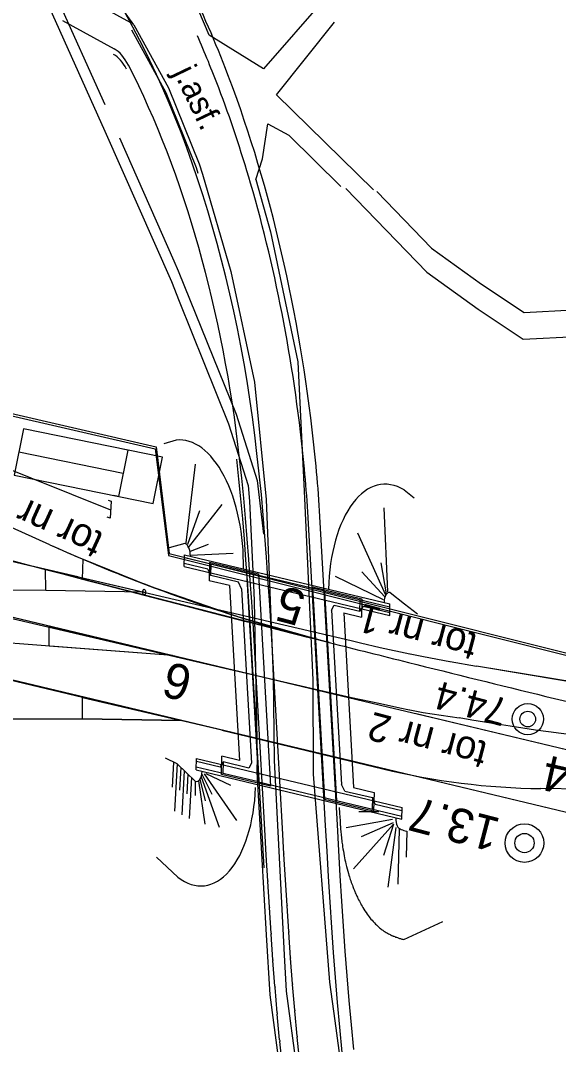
# Model space of a CAD drawing. Extents: x 6541740 to 6566395, y 5525066 to 5530361.
# Drawn here: x 6554145.9 to 6554168.66, y 5525293.06 to 5525336.42 of the extents above; entities that cross this region are included whole.
import ezdxf

# ---------------------------------------------------------------- set-up
doc = ezdxf.new("R2010")
doc.units = 0
for name, color, linetype in [('Domyślna', 7, 'Continuous'), ('TOR_PRZEK_P-komponent', 7, 'Continuous'), ('TOR_PS_OPIS_O-opisy odwodnienia', 7, 'Continuous'), ('TOR_PS_OPIS_T-symbole geometrii', 7, 'Continuous'), ('TOR_PS_OPIS_T-ukresy', 7, 'Continuous'), ('TOR_PS_T-rowy otwarte nieumocnione', 7, 'Continuous'), ('TOR_PS_T-wypelnienia', 7, 'Continuous'), ('TOR_RAMKI-ramka+tabelka 1', 7, 'Continuous'), ('TOR_W-warstwa dodatkowa 2', 7, 'Continuous')]:
    doc.layers.add(name, color=color, linetype=linetype)

# ---------------------------------------------------------------- blocks, each defined once
blk = doc.blocks.new('4010_1')
at = {"layer": 'Domyślna'}
for radius in [0.75, 0.375]:
    blk.add_circle((0, 0), radius, dxfattribs=at)
blk = doc.blocks.new('koziol 15+5')
at = {"layer": 'Domyślna'}
for p, q in [((15, 1), (14.3, 1)), ((15, 1), (15, -1)), ((20, 0), (20, 1)), ((0, 0), (15, 0)), ((15, -1), (14.3, -1))]:
    blk.add_line(p, q, dxfattribs=at)
blk.add_lwpolyline([(20, 1), (0, 1), (0, -1), (20, -1)], close=True, dxfattribs=at)
blk = doc.blocks.new('PM_2')
at = {"layer": 'Domyślna'}
blk.add_circle((0, 0), 0.25, dxfattribs=at)

msp = doc.modelspace()

# ---------------------------------------------------------------- linework, layer by layer
at = {"layer": 'TOR_PRZEK_P-komponent'}
for p, q in [((6554157.548, 5525308.274), (6554006.018, 5525344.541)), ((6554147.115, 5525310.771), (6554006.018, 5525344.541)), ((6554161.425, 5525307.346), (6554006.018, 5525344.541)), ((6554147.139, 5525314.22), (6554142.009, 5525316.524)), ((6554147.115, 5525310.771), (6554136.359, 5525313.345)), ((6554147.115, 5525310.771), (6554136.401, 5525313.335)), ((6554151.303, 5525312.499), (6554155.117, 5525311.172)), ((6554152.331, 5525309.523), (6554136.017, 5525310.789)), ((6554157.548, 5525308.274), (6554147.115, 5525310.771)), ((6554157.548, 5525308.274), (6554147.115, 5525310.771)), ((6554147.115, 5525310.771), (6554152.331, 5525309.523)), ((6554141.149, 5525309.561), (6554161.123, 5525304.78)), ((6554161.425, 5525307.346), (6554157.548, 5525308.274)), ((6554161.425, 5525307.346), (6554157.548, 5525308.274)), ((6554161.425, 5525307.346), (6554157.548, 5525308.274)), ((6554163.754, 5525306.789), (6554161.425, 5525307.346)), ((6554191.707, 5525300.099), (6554162.634, 5525307.057)), ((6554188.382, 5525300.894), (6554162.634, 5525307.057)), ((6554174.187, 5525304.292), (6554163.754, 5525306.789)), ((6554174.235, 5525304.28), (6554163.803, 5525306.777)), ((6554191.707, 5525300.099), (6554163.803, 5525306.777)), ((6554161.123, 5525304.78), (6554191.646, 5525297.475)), ((6554163.229, 5525304.276), (6554191.47, 5525297.517))]:
    msp.add_line(p, q, dxfattribs=at)
for points in [[(6554155.117, 5525311.172), (6554158.959, 5525310.078), (6554155.31, 5525311.008), (6554148.529, 5525312.766), (6554148.548, 5525313.609), (6554151.303, 5525312.499)], [(6554152.331, 5525309.523), (6554147.113, 5525309.928), (6554147.115, 5525310.771)]]:
    msp.add_lwpolyline(points, dxfattribs=at)
for centre, major_axis, start_param, end_param in [((6554272.656, 5529581.693), (-233.545, 4306.159), 2.967279, 2.979483), ((6554165.071, 5525539.713), (-12.555, 231.491), 2.884138, 2.984211), ((6554165.071, 5525539.713), (-12.555, 231.491), 2.884138, 2.89613), ((6554165.071, 5525539.713), (-12.555, 231.491), 2.89613, 2.984211), ((6554272.656, 5529581.693), (-233.545, 4306.159), 2.979483, 2.984211), ((6554272.656, 5529581.693), (-233.545, 4306.159), 2.984211, 2.985729), ((6554272.656, 5529581.693), (-233.545, 4306.159), 2.985729, 2.991005)]:
    msp.add_ellipse(centre, major_axis=major_axis, ratio=0.510219, start_param=start_param, end_param=end_param, dxfattribs=at)
at = {"layer": 'TOR_PS_OPIS_T-symbole geometrii'}
for p, q in [((6554147.253, 5525338.147), (6554150.549, 5525336.338)), ((6554147.68, 5525336.419), (6554149.866, 5525335.219)), ((6554158.806, 5525302.329), (6554158.051, 5525315.618)), ((6554159.305, 5525302.361), (6554158.55, 5525315.65)), ((6554156.985, 5525302.213), (6554156.487, 5525310.965)), ((6554156.205, 5525300.532), (6554155.614, 5525310.909)), ((6554156.236, 5525302.165), (6554155.739, 5525310.917)), ((6554156.298, 5525301.076), (6554156.236, 5525302.163)), ((6554157.047, 5525301.125), (6554156.985, 5525302.212)), ((6554156.362, 5525299.981), (6554156.299, 5525301.068)), ((6554157.11, 5525300.033), (6554157.047, 5525301.12)), ((6554156.429, 5525298.878), (6554156.363, 5525299.965)), ((6554157.177, 5525298.937), (6554157.111, 5525300.024)), ((6554156.501, 5525297.767), (6554156.43, 5525298.854)), ((6554157.248, 5525297.837), (6554157.178, 5525298.924)), ((6554156.579, 5525296.649), (6554156.503, 5525297.735)), ((6554157.325, 5525296.734), (6554157.249, 5525297.82)), ((6554157.409, 5525295.627), (6554157.326, 5525296.712)), ((6554156.664, 5525295.524), (6554156.581, 5525296.609)), ((6554156.758, 5525294.392), (6554156.668, 5525295.476)), ((6554157.502, 5525294.516), (6554157.411, 5525295.6)), ((6554157.605, 5525293.404), (6554157.504, 5525294.486)), ((6554156.864, 5525293.254), (6554156.763, 5525294.336)), ((6554156.981, 5525292.11), (6554156.87, 5525293.19)), ((6554157.719, 5525292.289), (6554157.608, 5525293.368))]:
    msp.add_line(p, q, dxfattribs=at)
for points in [[(6554156.487, 5525310.964), (6554156.429, 5525311.878), (6554156.369, 5525312.785), (6554156.307, 5525313.687), (6554156.24, 5525314.582), (6554156.168, 5525315.47), (6554156.089, 5525316.351), (6554156.002, 5525317.224), (6554155.904, 5525318.082)], [(6554155.615, 5525310.884), (6554155.557, 5525311.795), (6554155.498, 5525312.694), (6554155.437, 5525313.581), (6554155.372, 5525314.456), (6554155.302, 5525315.318), (6554155.225, 5525316.168), (6554155.142, 5525317.002), (6554155.047, 5525317.839)], [(6554155.74, 5525310.895), (6554155.682, 5525311.807), (6554155.622, 5525312.707), (6554155.561, 5525313.596), (6554155.496, 5525314.474), (6554155.425, 5525315.34), (6554155.349, 5525316.194), (6554155.265, 5525317.034), (6554155.169, 5525317.874)], [(6554159.515, 5525292.724), (6554159.406, 5525293.786), (6554159.309, 5525294.835), (6554159.221, 5525295.89), (6554159.14, 5525296.951), (6554159.066, 5525298.018), (6554158.996, 5525299.089), (6554158.931, 5525300.165), (6554158.868, 5525301.245), (6554158.806, 5525302.33)], [(6554160.007, 5525292.843), (6554159.899, 5525293.895), (6554159.804, 5525294.927), (6554159.717, 5525295.966), (6554159.637, 5525297.014), (6554159.563, 5525298.069), (6554159.495, 5525299.132), (6554159.43, 5525300.202), (6554159.367, 5525301.279), (6554159.305, 5525302.363)]]:
    msp.add_lwpolyline(points, dxfattribs=at)
for centre, major_axis, start_param, end_param in [((6554139.689, 5525313.568), (-1.756, 32.37), 4.824583, 5.588672), ((6554139.863, 5525313.698), (-1.993, 36.749), 5.240005, 5.375002), ((6554139.689, 5525313.568), (-1.96, 36.137), 5.270787, 5.346125), ((6554149.615, 5525332.866), (-0.119, 2.202), 5.429669, 5.976121), ((6554149.615, 5525332.866), (-0.133, 2.447), 5.429669, 5.976121), ((6554139.689, 5525313.568), (-1.676, 30.902), 4.824583, 5.429669), ((6554139.689, 5525313.568), (-1.96, 36.137), 5.141865, 5.270787), ((6554139.689, 5525313.568), (-2.013, 37.116), 4.791924, 5.237994), ((6554139.689, 5525313.568), (-1.96, 36.137), 4.791924, 5.141865), ((6554145.575, 5525314.817), (-1.38, 25.445), 4.71744, 4.791924), ((6554145.575, 5525314.817), (-1.327, 24.467), 4.71744, 4.791924), ((6554157.957, 5525301.184), (0.176, -3.254), 4.717851, 4.72032), ((6554157.957, 5525301.184), (0.097, -1.786), 4.717851, 4.72032), ((6554158.021, 5525300.097), (0.176, -3.254), 4.72032, 4.725259), ((6554158.021, 5525300.097), (0.097, -1.786), 4.72032, 4.725259), ((6554158.087, 5525299.01), (0.176, -3.254), 4.725259, 4.732666), ((6554158.087, 5525299.01), (0.097, -1.786), 4.725259, 4.732666), ((6554158.157, 5525297.923), (0.176, -3.254), 4.732666, 4.742543), ((6554158.157, 5525297.923), (0.097, -1.786), 4.732666, 4.742543), ((6554158.233, 5525296.837), (0.176, -3.254), 4.742543, 4.754888), ((6554158.233, 5525296.837), (0.097, -1.786), 4.742543, 4.754888), ((6554158.315, 5525295.752), (0.176, -3.254), 4.754888, 4.769703), ((6554158.315, 5525295.752), (0.097, -1.786), 4.754888, 4.769703), ((6554158.406, 5525294.668), (0.097, -1.786), 4.769703, 4.786987), ((6554158.406, 5525294.668), (0.176, -3.254), 4.769703, 4.786987), ((6554158.506, 5525293.586), (0.176, -3.254), 4.786987, 4.80674), ((6554158.506, 5525293.586), (0.097, -1.786), 4.786987, 4.80674)]:
    msp.add_ellipse(centre, major_axis=major_axis, ratio=0.510219, start_param=start_param, end_param=end_param, dxfattribs=at)
at = {"layer": 'TOR_PS_T-rowy otwarte nieumocnione'}
for p, q in [((6554142.794, 5525314.166), (6554148.327, 5525312.87)), ((6554168.968, 5525308.436), (6554165.194, 5525309.08)), ((6554154.42, 5525306.367), (6554161.231, 5525304.726)), ((6554199.007, 5525303.534), (6554167.908, 5525303.895))]:
    msp.add_line(p, q, dxfattribs=at)
for points in [[(6554103.213, 5525341.389), (6554107.185, 5525338.304), (6554111.172, 5525335.328), (6554114.839, 5525332.598), (6554120.595, 5525328.786), (6554121.88, 5525327.885), (6554125.647, 5525325.851), (6554128.763, 5525324.292), (6554131.931, 5525322.933), (6554141.308, 5525319.065), (6554149.714, 5525315.702)], [(6554100.477, 5525323.441), (6554103.102, 5525323.134), (6554105.707, 5525322.712), (6554108.194, 5525322.227), (6554110.495, 5525321.725), (6554113.375, 5525321.069), (6554125.264, 5525318.285), (6554128.426, 5525317.551), (6554136.762, 5525315.581), (6554146.963, 5525313.188), (6554153.767, 5525311.597), (6554159.892, 5525310.162), (6554159.892, 5525310.162), (6554160.286, 5525310.062), (6554161.123, 5525309.872), (6554162.378, 5525309.602), (6554162.379, 5525309.602), (6554162.943, 5525309.488), (6554164.07, 5525309.275), (6554164.071, 5525309.275), (6554165.194, 5525309.08), (6554165.194, 5525309.08)], [(6554098.464, 5525319.047), (6554100.603, 5525319.224), (6554102.799, 5525319.345), (6554105.318, 5525319.375), (6554107.923, 5525319.268), (6554110.349, 5525319.044), (6554112.65, 5525318.717), (6554115.593, 5525318.144), (6554119.723, 5525317.204), (6554128.057, 5525315.232), (6554136.392, 5525313.255), (6554137.46, 5525313.006), (6554144.268, 5525311.397), (6554153.756, 5525309.172), (6554159.899, 5525307.754), (6554161.131, 5525307.5), (6554161.954, 5525307.313), (6554162.364, 5525307.229), (6554162.366, 5525307.228), (6554162.935, 5525307.122), (6554163.314, 5525307.058), (6554164.071, 5525306.941), (6554164.072, 5525306.941), (6554164.452, 5525306.887)], [(6554154.42, 5525306.367), (6554148.523, 5525307.754), (6554140.173, 5525309.737), (6554133.36, 5525311.347), (6554115.822, 5525315.521), (6554111.041, 5525316.409), (6554107.492, 5525316.535), (6554103.892, 5525316.543), (6554099.33, 5525316.505)], [(6554149.613, 5525316.111), (6554149.737, 5525316.061), (6554149.69, 5525315.342), (6554149.566, 5525315.392)], [(6554151.131, 5525312.214), (6554146.968, 5525312.284), (6554144.262, 5525312.294), (6554140.101, 5525312.382)], [(6554151.131, 5525312.214), (6554146.968, 5525312.284), (6554144.262, 5525312.294), (6554140.101, 5525312.382)], [(6554192.925, 5525304.348), (6554190.643, 5525304.695), (6554189.694, 5525304.895), (6554189.677, 5525304.899), (6554185.348, 5525305.756), (6554165.194, 5525309.08)], [(6554098.921, 5525306.506), (6554100.881, 5525306.616), (6554103.078, 5525306.7), (6554107.887, 5525306.811), (6554111.935, 5525306.853), (6554115.391, 5525306.866), (6554123.708, 5525306.83), (6554133.482, 5525306.851), (6554148.524, 5525306.853), (6554152.691, 5525306.774)]]:
    msp.add_lwpolyline(points, dxfattribs=at)
for points in [[(6554151.131, 5525312.214), (6554146.968, 5525312.286), (6554146.963, 5525313.189)], [(6554152.691, 5525306.774), (6554148.524, 5525306.854), (6554148.523, 5525307.755)]]:
    msp.add_lwpolyline(points, close=True, dxfattribs=at)
for centre, radius, start, end in [((6554181.646, 5525405.409), 100, 260.10015, 270.11432), ((6554168.255, 5525333.893), 30, 256.4589, 269.3363)]:
    msp.add_arc(centre, radius, start, end, dxfattribs=at)
at = {"layer": 'TOR_PS_T-wypelnienia'}
for p, q in [((6554149.476, 5525332.847), (6554145.42, 5525341.912)), ((6554145.186, 5525341.277), (6554149.47, 5525331.726)), ((6554150.702, 5525336.241), (6554149.577, 5525337.806)), ((6554158.86, 5525337.443), (6554156.179, 5525334.37)), ((6554153.884, 5525335.796), (6554153.444, 5525336.824)), ((6554156.725, 5525333.277), (6554159.178, 5525336.349)), ((6554156.179, 5525334.37), (6554153.884, 5525335.796)), ((6554156.725, 5525333.277), (6554160.83, 5525329.25)), ((6554156.144, 5525330.557), (6554156.357, 5525332.041)), ((6554156.357, 5525332.041), (6554157.249, 5525331.567)), ((6554149.47, 5525331.726), (6554152.282, 5525325.36)), ((6554150.086, 5525331.45), (6554152.388, 5525326.238)), ((6554157.249, 5525331.567), (6554159.448, 5525329.387)), ((6554155.854, 5525329.688), (6554156.144, 5525330.557)), ((6554152.282, 5525325.36), (6554152.615, 5525324.533)), ((6554156.298, 5525297.705), (6554156.444, 5525295.162)), ((6554157.06, 5525296.859), (6554157.141, 5525295.313)), ((6554156.444, 5525295.162), (6554157.051, 5525290.685)), ((6554157.141, 5525295.313), (6554157.728, 5525290.98)), ((6554159.193, 5525294.054), (6554159.504, 5525291.757))]:
    msp.add_line(p, q, dxfattribs=at)
for points in [[(6554150.702, 5525336.241), (6554152.163, 5525333.561), (6554153.464, 5525330.355), (6554153.594, 5525329.912)], [(6554150.6, 5525336.027), (6554152.051, 5525333.363), (6554153.336, 5525330.197), (6554153.406, 5525329.96)], [(6554153.594, 5525329.912), (6554154.801, 5525325.795), (6554155.799, 5525321.104), (6554156.293, 5525316.135), (6554156.591, 5525308.647), (6554156.63, 5525305.085), (6554157.06, 5525296.859)], [(6554155.854, 5525329.688), (6554156.475, 5525327.466), (6554157.633, 5525321.97), (6554157.894, 5525316.492), (6554158.27, 5525308.495), (6554158.275, 5525304.511), (6554158.971, 5525295.691), (6554159.193, 5525294.054)], [(6554159.666, 5525329.311), (6554163.085, 5525325.758), (6554165.255, 5525324.196), (6554167.165, 5525322.921), (6554169.406, 5525323.042), (6554171.258, 5525323.917), (6554172.825, 5525325.293), (6554173.843, 5525325.583)], [(6554160.975, 5525329.181), (6554163.286, 5525326.78), (6554165.409, 5525325.251), (6554167.209, 5525324.049), (6554169.286, 5525324.161), (6554171.033, 5525324.987), (6554172.63, 5525326.389), (6554173.731, 5525326.698)], [(6554152.388, 5525326.238), (6554152.575, 5525325.815), (6554155.019, 5525319.742), (6554155.91, 5525316.945), (6554156.177, 5525314.67)], [(6554152.615, 5525324.533), (6554154.705, 5525319.34), (6554155.538, 5525316.724), (6554155.591, 5525316.066)], [(6554155.591, 5525316.066), (6554155.753, 5525312.512), (6554155.783, 5525311.859), (6554155.906, 5525305.229), (6554155.902, 5525304.593), (6554156.298, 5525297.705)]]:
    msp.add_lwpolyline(points, dxfattribs=at)
at = {"layer": 'TOR_W-warstwa dodatkowa 2'}
for p, q in [((6554130.54, 5525323.158), (6554151.594, 5525318.275)), ((6554130.542, 5525323.255), (6554151.634, 5525318.364)), ((6554151.634, 5525318.364), (6554152.195, 5525313.851)), ((6554152.486, 5525318.647), (6554151.969, 5525318.493)), ((6554151.594, 5525318.275), (6554152.155, 5525313.763)), ((6554152.91, 5525314.295), (6554153.307, 5525317.628)), ((6554162.129, 5525316.539), (6554162.55, 5525316.207)), ((6554153.01, 5525314.103), (6554154.43, 5525315.928)), ((6554161.44, 5525312.221), (6554161.28, 5525315.785)), ((6554152.986, 5525314.243), (6554153.485, 5525315.669)), ((6554161.356, 5525312.083), (6554160.175, 5525314.716)), ((6554152.848, 5525314.276), (6554152.195, 5525314.082)), ((6554153.09, 5525313.952), (6554153.849, 5525314.243)), ((6554152.155, 5525313.763), (6554191.772, 5525303.829)), ((6554152.195, 5525313.851), (6554191.795, 5525303.921)), ((6554152.826, 5525313.3), (6554152.837, 5525313.79)), ((6554158.768, 5525312.249), (6554152.834, 5525313.669)), ((6554152.837, 5525313.79), (6554161.53, 5525311.71)), ((6554153.086, 5525313.783), (6554154.9, 5525313.859)), ((6554152.826, 5525313.3), (6554161.519, 5525311.219)), ((6554153.832, 5525313.186), (6554152.829, 5525313.426)), ((6554153.832, 5525313.186), (6554153.952, 5525312.913)), ((6554153.902, 5525313.472), (6554153.884, 5525312.695)), ((6554155.972, 5525312.977), (6554153.902, 5525313.472)), ((6554153.952, 5525312.913), (6554153.963, 5525313.399)), ((6554161.385, 5525312.145), (6554161.153, 5525313.46)), ((6554154.748, 5525312.488), (6554153.884, 5525312.695)), ((6554155.117, 5525312.634), (6554153.952, 5525312.913)), ((6554155.468, 5525313.039), (6554155.972, 5525304.174)), ((6554155.972, 5525312.977), (6554156.483, 5525303.993)), ((6554161.26, 5525311.89), (6554159.224, 5525312.873)), ((6554161.318, 5525312.011), (6554160.34, 5525313.076)), ((6554154.748, 5525312.488), (6554155.168, 5525305.089)), ((6554155.256, 5525312.359), (6554155.117, 5525312.634)), ((6554155.256, 5525312.359), (6554155.676, 5525304.974)), ((6554158.257, 5525312.43), (6554158.768, 5525303.446)), ((6554158.257, 5525312.43), (6554160.337, 5525311.932)), ((6554158.768, 5525312.249), (6554159.272, 5525303.384)), ((6554158.768, 5525312.249), (6554161.528, 5525311.589)), ((6554160.262, 5525311.403), (6554160.273, 5525311.889)), ((6554160.337, 5525311.932), (6554160.32, 5525311.155)), ((6554159.064, 5525311.448), (6554159.176, 5525311.663)), ((6554159.064, 5525311.448), (6554159.484, 5525304.063)), ((6554159.176, 5525311.663), (6554160.262, 5525311.403)), ((6554160.393, 5525311.616), (6554160.262, 5525311.403)), ((6554160.393, 5525311.616), (6554161.522, 5525311.346)), ((6554161.519, 5525311.219), (6554161.53, 5525311.71)), ((6554159.572, 5525311.334), (6554159.992, 5525303.935)), ((6554159.572, 5525311.334), (6554160.32, 5525311.155)), ((6554152.525, 5525304.937), (6554152.032, 5525305.181)), ((6554152.371, 5525305.014), (6554152.315, 5525303.958)), ((6554152.525, 5525304.937), (6554152.42, 5525302.936)), ((6554153.335, 5525304.682), (6554153.346, 5525305.173)), ((6554154.347, 5525304.807), (6554153.344, 5525305.047)), ((6554153.346, 5525305.173), (6554162.04, 5525303.093)), ((6554154.347, 5525304.807), (6554154.478, 5525305.02)), ((6554154.403, 5525304.491), (6554154.421, 5525305.268)), ((6554155.168, 5525305.089), (6554154.421, 5525305.268)), ((6554154.478, 5525305.02), (6554154.467, 5525304.534)), ((6554155.564, 5525304.76), (6554154.478, 5525305.02)), ((6554155.676, 5525304.974), (6554155.564, 5525304.76)), ((6554152.677, 5525304.793), (6554152.626, 5525303.828)), ((6554152.828, 5525304.648), (6554152.73, 5525302.783)), ((6554152.979, 5525304.504), (6554152.935, 5525303.675)), ((6554153.335, 5525304.682), (6554162.028, 5525302.602)), ((6554155.972, 5525304.174), (6554153.338, 5525304.804)), ((6554153.574, 5525304.508), (6554153.996, 5525303.658)), ((6554153.672, 5525304.514), (6554155.033, 5525302.536)), ((6554153.743, 5525304.53), (6554154.78, 5525304.039)), ((6554156.483, 5525303.993), (6554154.403, 5525304.491)), ((6554153.13, 5525304.359), (6554153.039, 5525302.63)), ((6554153.296, 5525304.203), (6554153.29, 5525303.597)), ((6554153.43, 5525304.221), (6554153.697, 5525302.39)), ((6554153.494, 5525304.288), (6554153.716, 5525303.376)), ((6554153.543, 5525304.387), (6554154.301, 5525302.257)), ((6554155.972, 5525304.174), (6554159.272, 5525303.384)), ((6554159.623, 5525303.788), (6554159.484, 5525304.063)), ((6554159.623, 5525303.788), (6554160.788, 5525303.51)), ((6554159.992, 5525303.935), (6554160.856, 5525303.728)), ((6554160.856, 5525303.728), (6554160.838, 5525302.95)), ((6554158.768, 5525303.446), (6554160.838, 5525302.95)), ((6554159.272, 5525303.384), (6554162.031, 5525302.724)), ((6554160.788, 5525303.51), (6554160.777, 5525303.024)), ((6554160.908, 5525303.237), (6554160.788, 5525303.51)), ((6554160.908, 5525303.237), (6554162.037, 5525302.967)), ((6554161.057, 5525302.914), (6554160.21, 5525302.903)), ((6554162.028, 5525302.602), (6554162.04, 5525303.093)), ((6554161.632, 5525302.583), (6554159.671, 5525302.226)), ((6554161.685, 5525302.394), (6554159.984, 5525300.501)), ((6554161.669, 5525302.45), (6554160.31, 5525301.852)), ((6554161.686, 5525302.39), (6554161.257, 5525301.056)), ((6554161.779, 5525302.244), (6554161.436, 5525299.714)), ((6554161.922, 5525302.179), (6554161.867, 5525299.85)), ((6554162.248, 5525302.088), (6554162.221, 5525300.991)), ((6554162.124, 5525297.499), (6554163.769, 5525298.271))]:
    msp.add_line(p, q, dxfattribs=at)
for points in [[(6554161.542, 5525312.196), (6554162.141, 5525311.723), (6554162.694, 5525311.288)], [(6554159.479, 5525309.947), (6554159.479, 5525309.947)], [(6554153.291, 5525304.205), (6554152.525, 5525304.937)], [(6554152.554, 5525300.14), (6554151.659, 5525300.995)]]:
    msp.add_lwpolyline(points, dxfattribs=at)
for centre, major_axis, start_param, end_param in [((6554152.837, 5525313.79), (-0.264, 4.864), 4.561802, 6.318591), ((6554161.53, 5525311.71), (-0.275, 5.07), 5.944976, 7.703394), ((6554152.837, 5525313.79), (-0.027, 0.489), 4.561802, 6.132598), ((6554161.53, 5525311.71), (-0.027, 0.489), 6.132598, 7.703394), ((6554153.327, 5525304.701), (-0.027, 0.507), 2.898198, 4.529759), ((6554153.327, 5525304.701), (-0.267, 4.927), 2.725127, 4.529759)]:
    msp.add_ellipse(centre, major_axis=major_axis, ratio=0.510219, start_param=start_param, end_param=end_param, dxfattribs=at)
for points in [[(6554159.386, 5525303.096), (6554159.426, 5525302.384), (6554159.43, 5525302.332), (6554159.444, 5525302.144), (6554159.455, 5525302.008), (6554159.494, 5525301.665), (6554159.518, 5525301.479), (6554159.597, 5525301.016), (6554159.653, 5525300.737), (6554159.788, 5525300.247), (6554159.842, 5525300.071), (6554159.95, 5525299.768), (6554159.997, 5525299.645), (6554160.092, 5525299.422), (6554160.138, 5525299.322), (6554160.272, 5525299.048), (6554160.363, 5525298.889), (6554160.584, 5525298.544), (6554160.71, 5525298.384), (6554160.938, 5525298.133), (6554161.04, 5525298.042), (6554161.216, 5525297.9), (6554161.29, 5525297.85), (6554161.443, 5525297.754), (6554161.508, 5525297.723), (6554161.56, 5525297.698), (6554161.57, 5525297.694), (6554161.593, 5525297.683), (6554161.609, 5525297.675), (6554161.656, 5525297.655), (6554161.686, 5525297.642), (6554161.775, 5525297.606), (6554161.831, 5525297.586), (6554161.975, 5525297.538), (6554162.056, 5525297.516), (6554162.124, 5525297.499)], [(6554161.778, 5525302.662), (6554161.787, 5525302.521), (6554161.801, 5525302.266), (6554162.011, 5525302.155), (6554162.152, 5525302.112), (6554162.248, 5525302.088)]]:
    msp.add_open_spline(points, degree=3, dxfattribs=at)

# ---------------------------------------------------------------- block references
at = {"layer": 'TOR_PRZEK_P-komponent', "xscale": 0.2999999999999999, "rotation": -11.555935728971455}
msp.add_blockref('koziol 15+5', (6554145.831, 5525318.147), dxfattribs=at)
at = {"layer": 'TOR_PS_OPIS_T-ukresy', "xscale": 0.48963739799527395, "yscale": 0.25024885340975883, "rotation": 91.699535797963}
msp.add_blockref('PM_2', (6554151.131, 5525312.214), dxfattribs=at)
at = {"layer": 'TOR_RAMKI-ramka+tabelka 1'}
for p, xscale, yscale, rotation in [((6554167.361, 5525306.835), 0.8830865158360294, 0.8830865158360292, -41.35420539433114), ((6554167.221, 5525301.588), 1.0902302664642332, 1.0902302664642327, -40.95618777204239)]:
    msp.add_blockref('4010_1', p, dxfattribs=dict(at, xscale=xscale, yscale=yscale, rotation=rotation))

# ---------------------------------------------------------------- texts
at = {"layer": 'TOR_PS_OPIS_O-opisy odwodnienia'}
for s, height, rotation, p in [('tor nr 401a', 1.2, 155.5045, (6554149.488, 5525314.676)), ('5', 1.5, 165.1661, (6554158.05, 5525312.213)), ('tor nr 1', 1.2, 165.0915, (6554165.298, 5525310.432)), ('6', 1.5, 165.1661, (6554153.259, 5525309.002)), ('tor nr 2', 1.2, 165.0915, (6554165.72, 5525305.848)), ('4', 1.5, 167.1864, (6554169.273, 5525305.077))]:
    msp.add_text(s, height=height, rotation=rotation, dxfattribs=at).set_placement(p)
at = {"layer": 'TOR_PS_T-wypelnienia'}
msp.add_text('j.asf.', height=1, rotation=295.6656, dxfattribs=at).set_placement((6554152.356, 5525334.226))
at = {"layer": 'TOR_RAMKI-ramka+tabelka 1'}
for s, height, rotation, p in [('74.4', 1.181, 165.025, (6554166.595, 5525307.662)), ('13.7', 1.458, 165.4231, (6554166.271, 5525302.609))]:
    msp.add_text(s, height=height, rotation=rotation, dxfattribs=at).set_placement(p)

doc.saveas('drawing.dxf')
